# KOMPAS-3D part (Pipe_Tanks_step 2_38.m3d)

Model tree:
1. X Axis
2. Y Axis
3. Z Axis  (labels: Valve Dy 50; Pipe Dn 50)
     Òîëùèíà ñòåíêè 1 = 1

Referenced files in C:\Documents and Settings\kashirsky\Мои документы\Camtasia Studio\Pipelines3D\Tanks\: Tanks_step 2.a3d
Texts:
  Pipe Dn 50
  Steel ASTM A295
  Three Point Plane
  Plane at Angle
  Line and Point Plane
  Axis through Two Vertices
  Axis of Feature
  Axis of Conical Surface
  Axis through Edge
  Trim by Surface
  Trim by Sketch
  Feature with No History
  Intersection Axis of Two Planes
  Two Line Plane
  Line and Face Plane
  Bend by line
  Hole in sheet body
  Cut in sheet body
  Point in CM
  Linear Dimension from Line to Point
  Surface Finish Symbol
  Geometric Tolerance Symbol
  Leader #1
  Leader #2
  Leader #3
  Shape Deviations and Datum
  Node point number
  Mark of coordination axis
  Node point designation
  Mark/Reference designation with leader
  Mark/reference designation on line
  Mark/Reference designation without leader
  Valve Dy 50
  Plane of section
